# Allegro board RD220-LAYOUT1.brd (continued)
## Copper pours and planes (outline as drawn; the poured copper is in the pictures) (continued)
SIGN00122 on BOTTOM: 43.1,60.39 42.92,60.21 42.67,60.14 31.1,60.14 30.85,60.21 30.67,60.39 30.6,60.64 30.6,87.5 30.67,87.75 30.85,87.93 31.1,88 42.67,88 42.92,87.93 43.1,87.75 43.17,87.5 43.17,60.64 ; 12 cut-outs
SIGN00122 on BOTTOM: 33.7,33.88 33.83,33.21 34.21,32.64 36.84,30.02 37.41,29.64 38.08,29.51 39.93,29.51 40.07,29.5 40.2,29.5 45.82,29.5 45.94,29.5 46.07,29.51 50.55,29.51 50.66,29.46 50.7,29.36 50.7,18.75 50.69,18.68 50.68,18.6 50.62,18.53 50.54,18.5 29.65,18.5 29.54,18.54 29.5,18.65 29.5,42.71 29.51,42.76 29.54,42.81 34.13,47.4 34.17,47.43 34.23,47.44 57.85,47.44 57.96,47.4 58,47.29 58,44.79 57.99,44.74 57.96,44.69 55.81,42.55 55.76,42.51 55.71,42.5 38.07,42.5 37.41,42.37 36.84,41.99 34.21,39.36 33.83,38.79 33.7,38.13 ; 8 cut-outs
SIGN00122 on CONDUCTIVE2: 30.67,87.75 30.85,87.93 31.1,88 42.67,88 42.92,87.93 43.1,87.75 43.17,87.5 43.17,57.77 45.97,54.97 46.01,54.96 46.04,54.94 46.51,54.72 47.02,54.64 54.15,54.64 54.26,54.6 54.3,54.49 54.3,48.3 55.96,46.64 55.99,46.6 56,46.54 56,42.81 55.99,42.75 55.96,42.71 55.79,42.54 55.75,42.51 55.69,42.5 38.07,42.5 37.41,42.37 36.84,41.99 34.21,39.36 33.83,38.79 33.7,38.12 33.7,33.87 33.83,33.21 34.21,32.64 36.84,30.01 37.41,29.63 38.08,29.5 50.55,29.5 50.66,29.46 50.7,29.35 50.7,18.75 50.69,18.68 50.68,18.61 50.63,18.53 50.54,18.5 29.65,18.5 29.54,18.54 29.5,18.65 29.5,56.31 29.45,56.71 29.3,57.12 29.3,57.15 29.3,71.93 29.31,71.99 29.34,72.04 29.6,72.3 30.34,73.4 30.6,74.7 30.6,87.5 ; 20 cut-outs
SIGN00122 on CONDUCTIVE3: 57.85,47.44 57.96,47.4 58,47.29 58,44.79 57.99,44.74 57.96,44.69 55.81,42.54 55.76,42.51 55.71,42.5 38.07,42.5 37.41,42.37 36.84,41.99 34.21,39.36 33.83,38.79 33.7,38.12 33.7,33.88 33.83,33.21 34.21,32.64 36.84,30.02 37.41,29.64 38.08,29.51 39.93,29.51 40.07,29.5 40.2,29.5 45.82,29.5 45.94,29.5 46.07,29.51 50.55,29.51 50.66,29.46 50.7,29.36 50.7,18.75 50.69,18.68 50.68,18.61 50.63,18.53 50.54,18.5 29.65,18.5 29.54,18.54 29.5,18.65 29.5,42.71 29.51,42.76 29.54,42.81 34.13,47.4 34.17,47.43 34.23,47.44 ; 8 cut-outs
SIGN00122 on CONDUCTIVE3: 43.1,60.39 42.92,60.21 42.67,60.14 31.1,60.14 30.85,60.21 30.67,60.39 30.6,60.64 30.6,87.5 30.67,87.75 30.85,87.93 31.1,88 42.67,88 42.92,87.93 43.1,87.75 43.17,87.5 43.17,60.64 ; 12 cut-outs
SIGN00123 on TOP (solid shape): 20.63,85.75 21.22,85.43 20.96,84.81 21.04,84.15 20.39,84 19.38,84.56 19.2,84.75 19.13,85 19.23,85.31 19.51,85.49
SIGN00220 on TOP: 61.11,101.49 61.14,101.45 61.15,101.39 61.15,97.65 61.11,97.54 61,97.5 59.9,97.5 59.79,97.54 59.75,97.65 59.75,98.9 56.75,98.9 56.75,97.65 56.71,97.54 56.6,97.5 51.75,97.5 51.64,97.54 51.6,97.65 51.6,108 51.64,108.11 51.75,108.15 57.55,108.15 57.66,108.11 57.7,108 57.7,104.9 ; 7 cut-outs
SIGN00224 on TOP: 45.05,115.9 44.94,115.94 44.9,116.05 44.9,119.55 44.94,119.66 45.05,119.7 47,119.7 47.11,119.66 47.15,119.55 47.15,116.05 47.11,115.94 47,115.9
SIGN00225 on TOP: 47.2,105 47.42,103.76 48.06,102.68 48.09,102.63 48.1,102.58 48.1,99.42 48.09,99.37 47.42,98.24 47.2,97 47.2,91.65 47.16,91.54 47.05,91.5 31.1,91.5 30.93,91.5 30.76,91.49 30.65,91.52 30.6,91.64 30.6,114.65 30.75,115 31.1,115.15 39.12,115.15 39.7,114.56 40.28,115.15 41,115.15 42.5,113.65 47.05,113.65 47.16,113.61 47.2,113.5 ; 5 cut-outs
SIGN00227 on TOP: 8.6,128.55 4.9,128.55 4.65,128.62 4.47,128.8 4.4,129.05 4.4,134.5 4.47,134.75 4.65,134.93 4.9,135 15.85,135 16.1,134.93 16.28,134.75 16.35,134.5 16.35,127.75 16.28,127.5 16.1,127.32 15.85,127.25 9.96,127.25 9.9,127.26 9.86,127.29 ; 10 cut-outs
SIGN00230 on TOP: 76.55,103 76.44,103.04 76.4,103.15 76.4,107.2 76.44,107.31 76.55,107.35 78.95,107.35 79.06,107.31 79.1,107.2 79.1,103.15 79.06,103.04 78.95,103
SIGN00231 on TOP: 82.45,88.9 82.34,88.94 82.3,89.05 82.3,93.8 82.34,93.91 82.45,93.95 85.7,93.95 85.81,93.91 85.85,93.8 85.85,91.26 85.84,91.2 85.81,91.16 83.59,88.94 83.55,88.91 83.49,88.9
SIGN00232 on TOP: 82.8,106.3 82.69,106.34 82.65,106.45 82.65,109.6 82.69,109.71 82.8,109.75 85.7,109.75 85.81,109.71 85.85,109.6 85.85,106.45 85.81,106.34 85.7,106.3
SIGN00233 on TOP: 82.8,98.55 82.69,98.59 82.65,98.7 82.65,101.55 82.69,101.66 82.8,101.7 85.7,101.7 85.81,101.66 85.85,101.55 85.85,98.7 85.81,98.59 85.7,98.55
VP_DC on TOP: 59.15,61.16 59.16,61.21 59.19,61.26 67.54,69.61 67.59,69.64 67.64,69.65 97.19,69.65 97.25,69.64 97.29,69.61 98.16,68.74 98.19,68.7 98.2,68.64 98.2,57.96 98.19,57.9 98.16,57.86 97.44,57.14 97.4,57.11 97.34,57.1 81.31,57.1 80.64,56.97 80.07,56.59 74.46,50.98 74.42,50.95 74.36,50.94 59.3,50.94 59.19,50.98 59.15,51.09 ; 4 cut-outs
VP_DC on TOP: 40.3,120.6 39.7,121.19 39.1,120.6 36.8,120.6 36.69,120.64 36.65,120.75 36.65,126.31 36.69,126.42 36.8,126.46 47.7,126.46 47.81,126.42 47.85,126.31 47.85,122.45 47.81,122.34 47.7,122.3 42.5,122.3 40.8,120.6 ; 3 cut-outs
VP_DC on TOP: 77.05,109.65 76.94,109.69 76.9,109.8 76.9,117.3 76.97,117.55 77.15,117.73 77.4,117.8 85.35,117.8 85.6,117.73 85.78,117.55 85.85,117.3 85.85,114.45 85.81,114.34 85.7,114.3 81.68,114.3 79.15,111.77 79.15,109.8 79.11,109.69 79,109.65
VP_DC on TOP: 26,45.98 26,27.07 26,27.05 26,21.45 26,21.43 26,18.65 25.96,18.54 25.85,18.5 20.05,18.5 19.94,18.54 19.9,18.65 19.9,46.12 19.91,46.18 19.94,46.22 24.18,50.46 24.22,50.49 24.28,50.5 25.85,50.5 25.96,50.46 26,50.35 26,46.02 ; 8 cut-outs
VP_DC on TOP, BOTTOM: 68.45,137.2 68.51,137.19 68.56,137.16 69.91,135.81 69.94,135.76 69.95,135.7 69.95,132.8 69.88,132.55 69.7,132.37 69.45,132.3 53.5,132.3 53.25,132.37 53.07,132.55 53,132.8 53,136.7 53.07,136.95 53.25,137.13 53.5,137.2 ; 8 cut-outs
VP_DC on BOTTOM: 36.65,126.31 36.69,126.42 36.8,126.46 45.51,126.46 45.56,126.45 45.61,126.42 47.01,125.02 47.04,124.97 47.05,124.92 47.05,122.45 47.01,122.34 46.9,122.3 43.5,122.3 41.84,120.64 41.82,120.62 41.79,120.61 40.3,120.6 39.7,121.19 39.1,120.6 36.8,120.6 36.69,120.64 36.65,120.75 ; 3 cut-outs
VP_DC on BOTTOM: 164.85,115.91 164.72,116.58 164.34,117.14 161.64,119.84 161.08,120.22 160.41,120.35 147.45,120.35 147.34,120.39 147.3,120.5 147.3,143.85 147.34,143.96 147.45,144 163.7,144 164.05,143.85 164.2,143.5 164.2,140 166.73,133.06 173.21,129.31 173.25,129.22 173.25,60 173.1,59.65 172.75,59.5 143.95,59.5 143.28,59.37 142.72,58.99 138.02,54.29 137.97,54.26 137.91,54.25 114.7,54.25 114.67,54.25 114.64,54.26 108.95,56.62 108.11,56.97 107.78,57.07 107.44,57.1 81.31,57.1 80.64,56.97 80.07,56.59 74.46,50.98 74.42,50.95 74.36,50.94 33.45,50.94 32.78,50.81 32.21,50.43 26.51,44.73 26.51,44.73 26.13,44.16 26,43.49 26,18.65 25.96,18.54 25.85,18.5 20.05,18.5 19.94,18.54 19.9,18.65 19.9,46.12 19.91,46.18 30.32,56.6 30.36,56.63 30.42,56.64 53.85,56.64 54.52,56.77 55.08,57.15 67.54,69.61 67.59,69.64 67.64,69.65 160.41,69.65 161.08,69.78 161.64,70.16 164.34,72.86 164.72,73.42 164.85,74.09 ; 36 cut-outs
VP_DC on BOTTOM, CONDUCTIVE3: 79.25,114.2 78.68,114.43 78.45,115 78.45,117 78.68,117.57 79.25,117.8 81.25,117.8 81.82,117.57 82.05,117 82.05,115 81.82,114.43 81.25,114.2
VP_DC on CONDUCTIVE2: 26,45.98 26,27.07 26,27.05 26,21.45 26,21.43 26,18.65 25.96,18.54 25.85,18.5 20.05,18.5 19.94,18.54 19.9,18.65 19.9,46.12 19.91,46.18 19.94,46.22 24.18,50.46 24.22,50.49 24.28,50.5 25.85,50.5 25.96,50.46 26,50.35 26,46.02 ; 8 cut-outs
VP_DC on CONDUCTIVE2: 44.25,136.7 44.4,137.05 44.75,137.2 68.45,137.2 68.51,137.19 83.75,121.96 83.83,121.86 83.9,121.61 83.9,121.1 83.83,120.85 83.65,120.67 83.4,120.6 40.3,120.6 39.7,121.19 39.1,120.6 36.8,120.6 36.69,120.64 36.65,120.75 36.65,125.96 36.8,126.31 37.15,126.46 39.7,126.46 41.78,127.36 42.54,129.49 42.56,129.56 42.6,129.61 43.82,131.18 44.25,133.12 ; 11 cut-outs
VP_DC on CONDUCTIVE2: 164.85,115.91 164.72,116.57 164.34,117.14 161.64,119.84 161.07,120.22 160.41,120.35 147.45,120.35 147.34,120.39 147.3,120.5 147.3,143.85 147.34,143.96 147.45,144 163.7,144 164.05,143.85 164.2,143.5 164.2,140 166.73,133.06 173.21,129.31 173.25,129.22 173.25,60 173.1,59.65 172.75,59.5 143.7,59.5 143.67,59.49 143.64,59.48 143.14,59.3 142.72,58.99 138.02,54.29 137.97,54.26 137.91,54.25 114.7,54.25 114.67,54.25 114.64,54.26 108.11,56.97 107.78,57.07 107.44,57.1 81.31,57.1 80.64,56.97 80.07,56.59 74.46,50.98 74.42,50.95 74.36,50.94 59.3,50.94 59.19,50.98 59.15,51.09 59.15,61.16 59.16,61.21 59.19,61.26 67.54,69.61 67.59,69.64 67.64,69.65 160.41,69.65 161.07,69.78 161.64,70.16 164.34,72.86 164.72,73.43 164.85,74.09 ; 28 cut-outs
VP_DC on CONDUCTIVE3: 68.45,137.2 68.51,137.19 68.56,137.16 69.91,135.81 69.94,135.76 69.95,135.7 69.95,132.8 69.88,132.55 69.7,132.37 69.45,132.3 53.5,132.3 53.25,132.37 53.07,132.55 53,132.8 53,136.7 53.07,136.95 53.25,137.13 53.5,137.2 ; 8 cut-outs
VP_DC on CONDUCTIVE3: 36.65,126.31 36.69,126.42 36.8,126.46 45.51,126.46 45.56,126.45 45.61,126.42 47.01,125.02 47.04,124.97 47.05,124.92 47.05,122.45 47.01,122.34 46.9,122.3 43.6,122.3 41.94,120.64 41.9,120.61 41.84,120.6 40.3,120.6 39.7,121.19 39.1,120.6 36.8,120.6 36.69,120.64 36.65,120.75 ; 3 cut-outs
VP_DC on CONDUCTIVE3: 164.85,115.91 164.72,116.58 164.34,117.14 161.64,119.84 161.07,120.22 160.41,120.35 147.45,120.35 147.34,120.39 147.3,120.5 147.3,143.85 147.34,143.96 147.45,144 163.7,144 164.05,143.85 164.2,143.5 164.2,140 166.73,133.06 173.21,129.31 173.25,129.22 173.25,60 173.1,59.65 172.75,59.5 143.95,59.5 143.28,59.37 142.72,58.99 137.97,54.24 137.92,54.21 137.86,54.2 114.82,54.2 114.79,54.2 114.76,54.21 108.95,56.62 108.11,56.97 107.78,57.07 107.44,57.1 81.31,57.1 80.64,56.97 80.07,56.59 79.17,55.68 74.46,50.98 74.42,50.95 74.36,50.94 49.23,50.94 49.19,50.95 49.16,50.96 46.25,51.75 43.34,50.96 43.31,50.95 43.27,50.94 33.45,50.94 32.78,50.81 32.21,50.43 26.51,44.73 26.13,44.16 26,43.49 26,18.65 25.96,18.54 25.85,18.5 20.05,18.5 19.94,18.54 19.9,18.65 19.9,46.12 19.91,46.18 19.94,46.22 30.32,56.6 30.36,56.63 30.42,56.64 53.85,56.64 54.52,56.77 55.08,57.15 67.54,69.61 67.59,69.64 67.64,69.65 160.41,69.65 161.08,69.78 161.64,70.16 164.34,72.86 164.72,73.42 164.85,74.09 ; 36 cut-outs

Small or netless copper shapes (teardrops, artwork), in the pictures only: 20 on TOP, 6 on BOTTOM, 3 on CONDUCTIVE2, 3 on CONDUCTIVE3

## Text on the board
Ref Des/Silkscreen Top: C26 | C27 | C28 | R9 | R8 | Q2 | TP4 | TP5 | T1 | AC1 | Na | RY1 | C13 | AC2 | AC3 | R6 | R7 | TP7 | SNS | R28 | C31 | GATE | TP6 | R17 | R18 | R19 | C8 | FB | Np | TP11 | TP10 | C22 | C20 | R15 | TP8 | R13 | C21 | IC1 | R26 | C25 | C9 | CN6 | TP3 | C7 | C17 | C16 | 6 | 5 | 1 | TP1 | C15 | L1 | CN5 | 4 | C14 | 2 | 3 | CN1 | RV1 | CN2 | CN3 | RV2 | RV3 | TP12 | D4 | A20V | TP14 | AGND | C18 | C19 | CN7 | D1 | DA1 | P | TP9 | Q1 | D3 | ZD1 | N | C32 | C23 | R11 | D2 | R14 | R12 | C24 | R16 | R10 | ZD2 | R27 | C12 | R23 | R24 | R25 | R5 | R4 | TP2 | C11 | C10 | C5 | C2 | R1 | C4 | FL3 | C6 | FL1 | FL2 | R2 | FL6 | FL4 | FL5 | R3 | FL9 | CN4 | FL7 | FL8 | C1 | C3 | + | DC Output | L2 | AC Input | L3 | 16A 500V | 400V 3phase AC-DC | - | FG
